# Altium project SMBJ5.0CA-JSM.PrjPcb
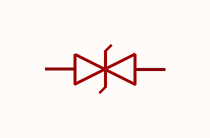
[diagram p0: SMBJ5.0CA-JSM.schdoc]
1 sheet, 1 parts. Net scope: global (net labels, ports and power ports of the same name join across sheets).

## Sheet SMBJ5.0CA-JSM.schdoc
size 127 x 101 mm

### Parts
D?  smbj5.0ca-jsm  [SMB_L4.4-W3.6-LS5.3-BI]  (value not drawn)

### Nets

Not connected (* = marked no-connect by the designer): D? 1 2

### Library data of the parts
D? = smbj5.0ca-jsm: 极性:双向;反向截止电压(Vrwm):5V;钳位电压:9.6V;峰值脉冲电流(Ipp):65.2A;峰值脉冲功率(Ppp):600W;击穿电压(VBR):7.07V;; Manufacturer: JSMSEMI(杰盛微); AddInBom: yes; ModelId: 0b05f1e84232498d868b1eafe1bb2917; ModelTransform: 210.2358,142.3979,0,0,0,0,0,0,0; Polarity: 双向; Reverse Stand-Off Voltage (Vrwm): 5V; Clamping Voltage: 9.6V; Peak Pulse Current (Ipp): 65.2A; Peak Pulse Power Dissipation (Ppp): 600W; Voltage - Breakdown: 7.07V; Reverse Leakage Current (Ir): 500uA; Number of Channels: 单路; Type: TVS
